// Mitsubishi GX Works2 project: 38.机械手臂工作（设定步骤值）   PLC: FX3U/FX3UC

PROGRAM MAIN
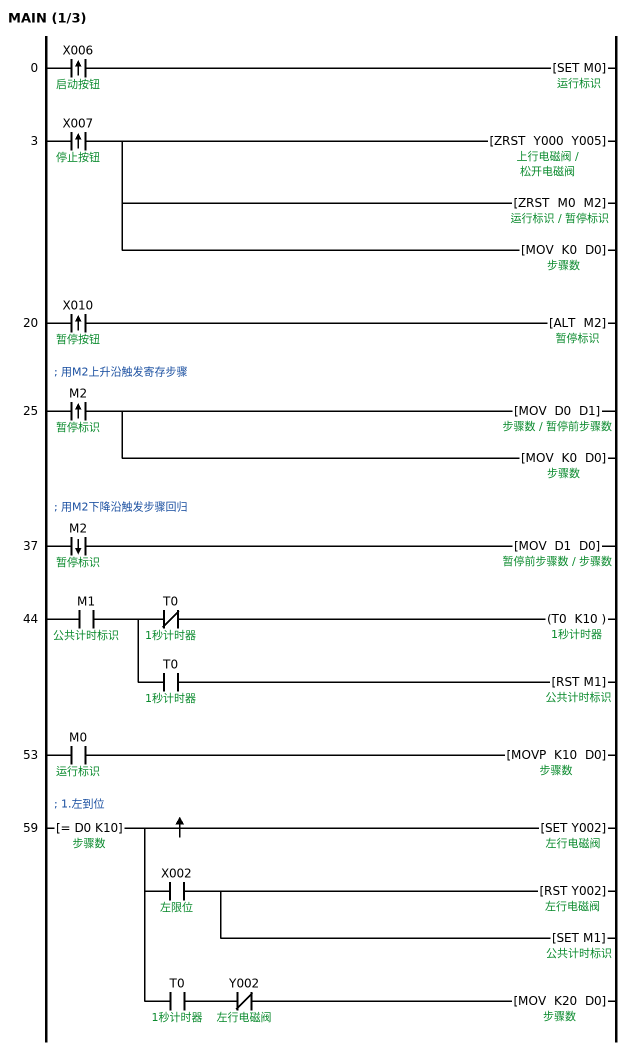
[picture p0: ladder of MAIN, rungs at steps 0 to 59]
0     LDP     X006  ; 启动按钮
      SET     M0  ; 运行标识
3     LDP     X007  ; 停止按钮
      ZRST    Y000 Y005  ; 上行电磁阀 / 松开电磁阀
      ZRST    M0 M2  ; 暂停标识
      MOV     K0 D0  ; 步骤数
20    LDP     X010  ; 暂停按钮
      ALT     M2
; 用M2上升沿触发寄存步骤
25    LDP     M2  ; 暂停标识
      MOV     D0 D1  ; 暂停前步骤数
      MOV     K0 D0
; 用M2下降沿触发步骤回归
37    LDF     M2  ; 暂停标识
      MOV     D1 D0
44    LD      M1  ; 公共计时标识
      MPS
      ANI     T0  ; 1秒计时器
      OUT     T0 K10  ; 1秒计时器
      MPP
      AND     T0  ; 1秒计时器
      RST     M1  ; 公共计时标识
53    LD      M0  ; 运行标识
      MOVP    K10 D0
; 1.左到位
59    LD=     D0 K10  ; 步骤数
      MPS
      MEP
      SET     Y002  ; 左行电磁阀
      MRD
      AND     X002  ; 左限位
      RST     Y002  ; 左行电磁阀
      SET     M1  ; 公共计时标识
      MPP
      AND     T0  ; 1秒计时器
      ANI     Y002  ; 左行电磁阀
      MOV     K20 D0
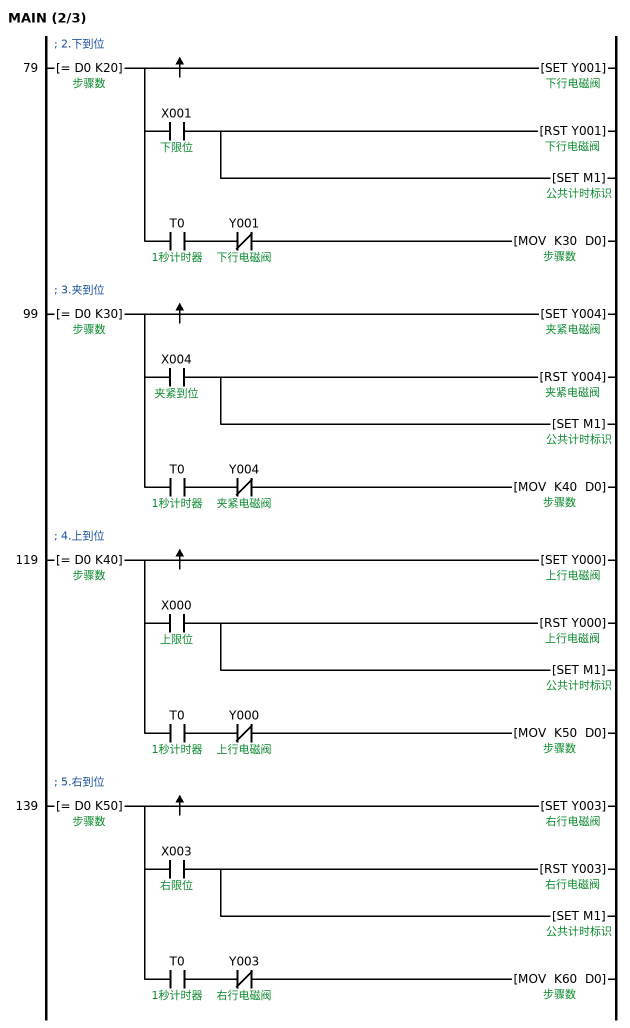
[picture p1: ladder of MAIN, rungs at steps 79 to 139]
; 2.下到位
79    LD=     D0 K20  ; 步骤数
      MPS
      MEP
      SET     Y001  ; 下行电磁阀
      MRD
      AND     X001  ; 下限位
      RST     Y001  ; 下行电磁阀
      SET     M1  ; 公共计时标识
      MPP
      AND     T0  ; 1秒计时器
      ANI     Y001  ; 下行电磁阀
      MOV     K30 D0
; 3.夹到位
99    LD=     D0 K30  ; 步骤数
      MPS
      MEP
      SET     Y004  ; 夹紧电磁阀
      MRD
      AND     X004  ; 夹紧到位
      RST     Y004  ; 夹紧电磁阀
      SET     M1  ; 公共计时标识
      MPP
      AND     T0  ; 1秒计时器
      ANI     Y004  ; 夹紧电磁阀
      MOV     K40 D0
; 4.上到位
119   LD=     D0 K40  ; 步骤数
      MPS
      MEP
      SET     Y000  ; 上行电磁阀
      MRD
      AND     X000  ; 上限位
      RST     Y000  ; 上行电磁阀
      SET     M1  ; 公共计时标识
      MPP
      AND     T0  ; 1秒计时器
      ANI     Y000  ; 上行电磁阀
      MOV     K50 D0
; 5.右到位
139   LD=     D0 K50  ; 步骤数
      MPS
      MEP
      SET     Y003  ; 右行电磁阀
      MRD
      AND     X003  ; 右限位
      RST     Y003  ; 右行电磁阀
      SET     M1  ; 公共计时标识
      MPP
      AND     T0  ; 1秒计时器
      ANI     Y003  ; 右行电磁阀
      MOV     K60 D0
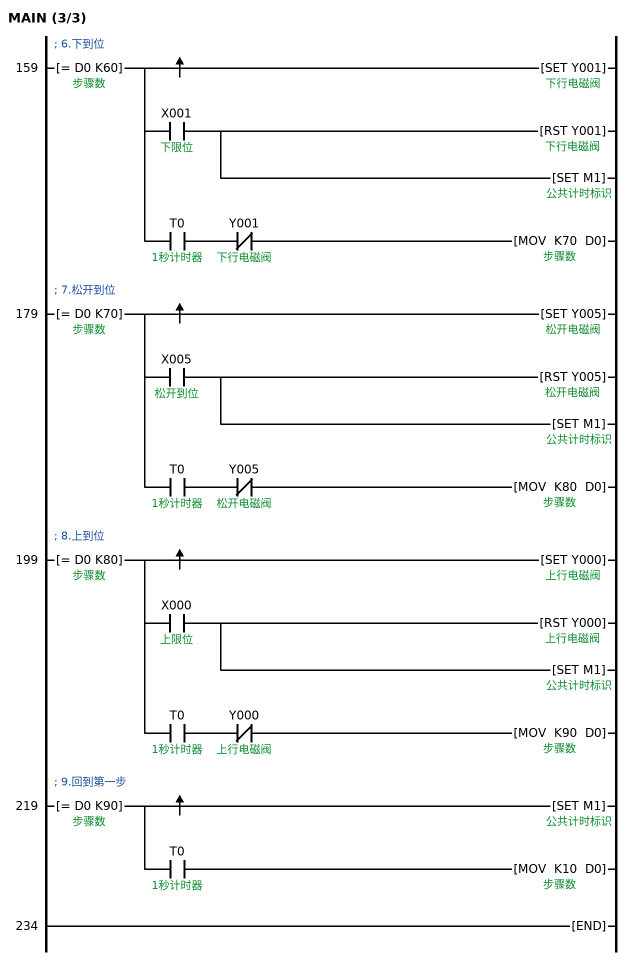
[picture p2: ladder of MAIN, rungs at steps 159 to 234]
; 6.下到位
159   LD=     D0 K60  ; 步骤数
      MPS
      MEP
      SET     Y001  ; 下行电磁阀
      MRD
      AND     X001  ; 下限位
      RST     Y001  ; 下行电磁阀
      SET     M1  ; 公共计时标识
      MPP
      AND     T0  ; 1秒计时器
      ANI     Y001  ; 下行电磁阀
      MOV     K70 D0
; 7.松开到位
179   LD=     D0 K70  ; 步骤数
      MPS
      MEP
      SET     Y005  ; 松开电磁阀
      MRD
      AND     X005  ; 松开到位
      RST     Y005  ; 松开电磁阀
      SET     M1  ; 公共计时标识
      MPP
      AND     T0  ; 1秒计时器
      ANI     Y005  ; 松开电磁阀
      MOV     K80 D0
; 8.上到位
199   LD=     D0 K80  ; 步骤数
      MPS
      MEP
      SET     Y000  ; 上行电磁阀
      MRD
      AND     X000  ; 上限位
      RST     Y000  ; 上行电磁阀
      SET     M1  ; 公共计时标识
      MPP
      AND     T0  ; 1秒计时器
      ANI     Y000  ; 上行电磁阀
      MOV     K90 D0
; 9.回到第一步
219   LD=     D0 K90  ; 步骤数
      MPS
      MEP
      SET     M1  ; 公共计时标识
      MPP
      AND     T0  ; 1秒计时器
      MOV     K10 D0
234   END
END_PROGRAM
